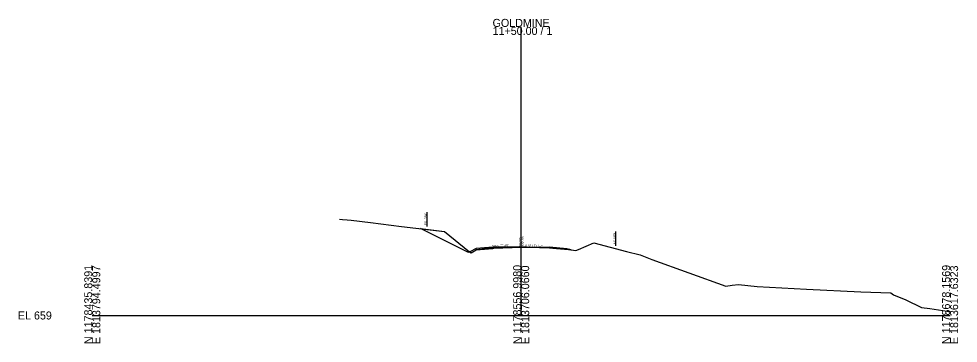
# Model space of a CAD drawing. Extents: x -26 to 1603, y -10 to 1590.
# Drawn here: x 1274.3 to 1602.8, y 990.3 to 1103.7 of the extents above; entities that cross this region are included whole.
import ezdxf

# ---------------------------------------------------------------- set-up
doc = ezdxf.new("R2010")
doc.units = 0
for name, color, linetype in [('Default', 7, 'Continuous'), ('RD_EX_RW', 7, 'Continuous'), ('RD_GPK_XS_Cell', 7, 'Continuous'), ('RD_XS_EarthShd', 7, 'Continuous'), ('RD_XS_ExGround', 7, 'Continuous'), ('RD_XS_Misc_Line', 7, 'Continuous'), ('RD_XS_Pave', 7, 'Continuous'), ('RD_XS_TX_Elev_EX', 7, 'Continuous'), ('RD_XS_TX_Slope', 7, 'Continuous')]:
    doc.layers.add(name, color=color, linetype=linetype)

msp = doc.modelspace()

# ---------------------------------------------------------------- linework, layer by layer
at = {"layer": 'Default'}
for p, q in [((1450, 1023.85), (1440.05, 1023.64)), ((1459.95, 1023.64), (1450, 1023.85))]:
    msp.add_line(p, q, dxfattribs=at)
at = {"layer": 'RD_EX_RW'}
for p, q in [((1417, 1036.11), (1417, 1031.11)), ((1483, 1029.37), (1483, 1024.37))]:
    msp.add_line(p, q, dxfattribs=at)
at = {"layer": 'RD_GPK_XS_Cell'}
for p, q in [((1450, 1000), (1450, 1100.87)), ((1300, 1000), (1450, 1000)), ((1450, 1000), (1600, 1000))]:
    msp.add_line(p, q, dxfattribs=at)
at = {"layer": 'RD_XS_EarthShd'}
for p, q in [((1440.05, 1023.64), (1434.25, 1022.96)), ((1459.95, 1023.64), (1460.95, 1023.58))]:
    msp.add_line(p, q, dxfattribs=at)
at = {"layer": 'RD_XS_ExGround'}
msp.add_lwpolyline([(1386.47, 1033.62), (1387.54, 1033.58), (1389.19, 1033.42), (1390.52, 1033.28), (1397.26, 1032.47), (1408.1, 1031.16), (1423.13, 1029.38), (1431.94, 1022.28), (1432.48, 1021.84), (1434.25, 1022.96), (1440.05, 1023.47), (1440.39, 1023.48), (1450, 1023.85), (1450.67, 1023.87), (1456.37, 1023.75), (1459.95, 1023.66), (1462.34, 1023.46), (1466.5, 1023.11), (1469.14, 1022.7), (1470.05, 1023.08), (1475.46, 1025.35), (1486.88, 1022.35), (1491.63, 1021.22), (1495.65, 1019.52), (1521.59, 1010.19), (1523.8, 1010.56), (1525.98, 1010.88), (1532.49, 1010.17), (1549.81, 1009.2), (1568.74, 1008.24), (1579.28, 1007.87), (1580.26, 1007.16), (1584.53, 1005.42), (1589.99, 1002.83), (1592.86, 1002.39), (1598.93, 1001.46), (1599.5, 1001.4), (1600, 1001.42)], dxfattribs=at)
at = {"layer": 'RD_XS_Misc_Line'}
for points in [[(1431.94, 1022.28), (1432, 1022.23), (1431.53, 1022), (1414.79, 1030.37), (1423.13, 1029.38)], [(1432.48, 1021.84), (1434.25, 1022.96), (1440.05, 1023.47), (1440.05, 1023.84), (1434.25, 1023.36), (1432, 1022.23)], [(1450, 1023.85), (1440.05, 1023.84), (1440.05, 1023.47), (1440.39, 1023.48)], [(1450.67, 1023.87), (1451.81, 1023.85), (1450, 1023.85)], [(1451.81, 1023.85), (1459.95, 1023.85), (1459.95, 1023.66), (1456.37, 1023.75)], [(1459.95, 1023.66), (1462.34, 1023.46), (1466.5, 1023.11), (1467.53, 1022.95), (1465.95, 1023.35), (1459.95, 1023.85)]]:
    msp.add_lwpolyline(points, close=True, dxfattribs=at)
at = {"layer": 'RD_XS_Pave'}
msp.add_line((1440.05, 1023.47), (1440.05, 1023.64), dxfattribs=at)

# ---------------------------------------------------------------- texts
at = {"layer": 'Default'}
msp.add_text('682.85', height=0.8, rotation=90, dxfattribs=at).set_placement((1450.91, 1024.25))
at = {"layer": 'RD_EX_RW'}
for p in [(1416.94, 1031.63), (1482.94, 1024.9)]:
    msp.add_text('EX. R/W', height=0.75, rotation=90, dxfattribs=at).set_placement(p)
at = {"layer": 'RD_GPK_XS_Cell'}
for s, p in [('GOLDMINE', (1440, 1100.87)), ('11+50.00 / 1', (1440, 1098.07)), ('EL 659', (1274, 998.6))]:
    msp.add_text(s, height=2.8, dxfattribs=at).set_placement(p)
for s, p in [('N 1178435.8391', (1300, 990)), ('E 1813794.4997', (1302.8, 990)), ('N 1178556.9980', (1450, 990)), ('E 1813706.0660', (1452.8, 990)), ('N 1178678.1569', (1600, 990)), ('E 1813617.6323', (1602.8, 990))]:
    msp.add_text(s, height=2.8, rotation=90, dxfattribs=at).set_placement(p)
at = {"layer": 'RD_XS_TX_Elev_EX'}
msp.add_text('682.85', height=0.8, rotation=90, dxfattribs=at).set_placement((1450, 1024.01))
at = {"layer": 'RD_XS_TX_Slope'}
for rotation, p in [(1.1916, (1439.71, 1023.88)), (358.8084, (1451.49, 1024.02))]:
    msp.add_text('0.021 FT./FT.', height=0.75, rotation=rotation, dxfattribs=at).set_placement(p)

doc.saveas('drawing.dxf')
